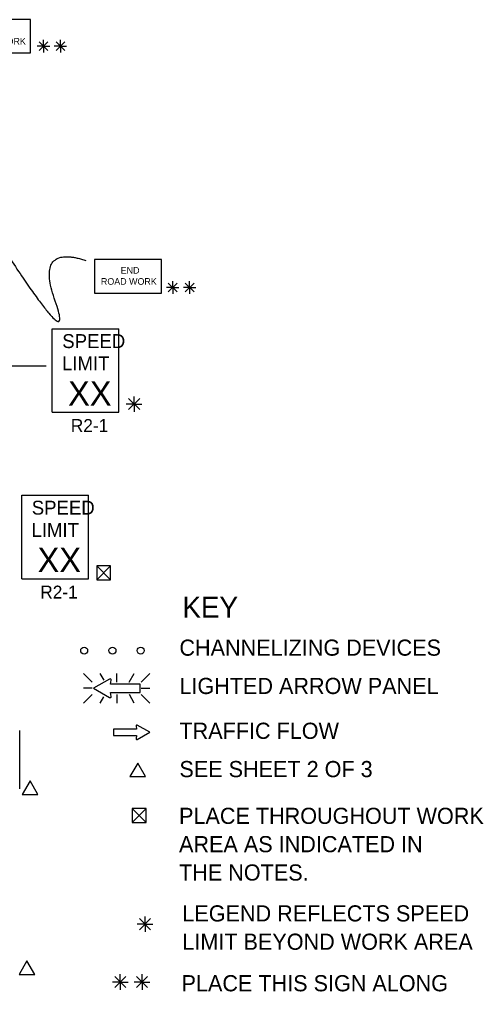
# Model space of a CAD drawing. Extents: x 16486 to 19505, y 5576 to 6998.
# Drawn here: x 17161 to 17428, y 6304 to 6864 of the extents above; entities that cross this region are included whole.
import ezdxf

# ---------------------------------------------------------------- set-up
doc = ezdxf.new("R2010")
doc.units = 0
for name, color, linetype in [('MT_SCRATCH_LEVEL_E', 7, 'Continuous'), ('TRAFFIC_SIGNS_PR', 7, 'Continuous'), ('TYPICAL_TEXT_DIMEN_EX', 7, 'Continuous'), ('TYPICAL_TEXT_DIMEN_PR', 7, 'Continuous')]:
    doc.layers.add(name, color=color, linetype=linetype)

msp = doc.modelspace()

# ---------------------------------------------------------------- linework, layer by layer
at = {"layer": 'MT_SCRATCH_LEVEL_E'}
for p, q in [((17235.64, 6453.62), (17228.4, 6457.73)), ((17228.03, 6455.48), (17214.78, 6455.48)), ((17214.78, 6455.48), (17214.78, 6451.73)), ((17227.72, 6457.25), (17228.03, 6455.48)), ((17228.4, 6449.48), (17235.64, 6453.62)), ((17214.78, 6451.73), (17228.03, 6451.73)), ((17228.03, 6451.73), (17227.72, 6449.95))]:
    msp.add_line(p, q, dxfattribs=at)
for centre, start, end in [((17228.18, 6457.33), 60.4248, 189.9638), ((17228.18, 6449.89), 170.0362, 299.7731)]:
    msp.add_arc(centre, 0.463, start, end, dxfattribs=at)
at = {"layer": 'TRAFFIC_SIGNS_PR'}
for p, q in [((17179.45, 6685.93), (17217.85, 6685.93)), ((17179.45, 6637.93), (17179.45, 6685.93)), ((17217.85, 6637.93), (17217.85, 6685.93)), ((17179.45, 6637.93), (17217.85, 6637.93)), ((17161.88, 6590.04), (17200.28, 6590.04)), ((17161.88, 6542.04), (17161.88, 6590.04)), ((17200.28, 6542.04), (17200.28, 6590.04)), ((17161.88, 6542.04), (17200.28, 6542.04)), ((17197.49, 6487.43), (17202.43, 6482.5)), ((17209.26, 6483.61), (17207.05, 6487.44)), ((17216.58, 6482.5), (17216.58, 6487.44)), ((17223.81, 6482.5), (17226.66, 6487.44)), ((17230.72, 6482.5), (17235.66, 6487.44)), ((17202.43, 6478.94), (17197.49, 6478.94)), ((17197.49, 6470.46), (17202.43, 6475.39)), ((17216.58, 6475.39), (17216.58, 6470.45)), ((17226.7, 6470.45), (17223.85, 6475.39)), ((17230.72, 6478.94), (17235.66, 6478.94)), ((17230.72, 6475.39), (17235.66, 6470.45)), ((17207, 6470.45), (17209.12, 6474.12)), ((17160.55, 6454.67), (17160.55, 6421.07))]:
    msp.add_line(p, q, dxfattribs=at)
for points in [[(17128.46, 6844.75), (17166.86, 6844.75), (17166.86, 6863.95), (17128.46, 6863.95)], [(17203.87, 6706.48), (17242.27, 6706.48), (17242.27, 6725.68), (17203.87, 6725.68)]]:
    msp.add_lwpolyline(points, close=True, dxfattribs=at)
for points in [[(17212.5, 6484.22), (17203.21, 6478.94), (17212.51, 6473.62)], [(17213.38, 6474.25), (17212.98, 6476.52), (17229.99, 6476.52), (17229.99, 6481.32), (17212.98, 6481.32), (17213.38, 6483.6)]]:
    msp.add_lwpolyline(points, dxfattribs=at)
for centre in [(17197.83, 6500.63), (17214.13, 6500.63), (17230.43, 6500.63)]:
    msp.add_circle(centre, 2, dxfattribs=at)
for centre, radius, start, end in [((17212.79, 6483.7), 0.598, 350.7308, 118.8916), ((17212.79, 6474.15), 0.597, 241.4833, 9.9593)]:
    msp.add_arc(centre, radius, start, end, dxfattribs=at)
at = {"layer": 'TYPICAL_TEXT_DIMEN_PR'}
for p, q in [((17171.86, 6851.12), (17176.96, 6846.02)), ((17176.96, 6851.12), (17171.86, 6846.02)), ((17174.41, 6848.57), (17174.41, 6852.14)), ((17181.61, 6851.12), (17186.71, 6846.02)), ((17186.71, 6851.12), (17181.61, 6846.02)), ((17184.16, 6848.57), (17184.16, 6852.14)), ((17174.41, 6848.57), (17170.79, 6848.57)), ((17174.41, 6848.57), (17176.96, 6848.57)), ((17174.41, 6848.57), (17177.99, 6848.57)), ((17174.41, 6848.57), (17174.41, 6844.97)), ((17184.16, 6848.57), (17180.53, 6848.57)), ((17184.16, 6848.57), (17186.71, 6848.57)), ((17184.16, 6848.57), (17187.74, 6848.57)), ((17184.16, 6848.57), (17184.16, 6844.97)), ((17248.82, 6709.68), (17245.19, 6709.68)), ((17246.27, 6712.23), (17251.37, 6707.13)), ((17251.37, 6712.23), (17246.27, 6707.13)), ((17248.82, 6709.68), (17248.82, 6713.25)), ((17248.82, 6709.68), (17251.37, 6709.68)), ((17248.82, 6709.68), (17252.4, 6709.68)), ((17248.82, 6709.68), (17248.82, 6706.08)), ((17258.57, 6709.68), (17254.94, 6709.68)), ((17261.12, 6712.23), (17256.01, 6707.13)), ((17256.02, 6712.23), (17261.12, 6707.13)), ((17258.57, 6709.68), (17258.57, 6713.25)), ((17258.57, 6709.68), (17261.12, 6709.68)), ((17258.57, 6709.68), (17262.15, 6709.68)), ((17258.57, 6709.68), (17258.57, 6706.08)), ((17142.7, 6664.64), (17175.9, 6664.64)), ((17142.7, 6664.64), (17175.9, 6664.64)), ((17142.7, 6664.64), (17175.9, 6664.64)), ((17226.64, 6642.55), (17222.11, 6642.55)), ((17223.45, 6645.73), (17229.83, 6639.36)), ((17229.83, 6645.73), (17223.45, 6639.36)), ((17226.64, 6642.55), (17226.64, 6647)), ((17226.64, 6642.55), (17229.83, 6642.55)), ((17226.64, 6642.55), (17231.12, 6642.55)), ((17226.64, 6642.55), (17226.64, 6638.05)), ((17205.07, 6549.36), (17213.07, 6541.36)), ((17205.07, 6541.36), (17213.07, 6549.36)), ((17225.49, 6409.76), (17233.49, 6401.76)), ((17225.49, 6401.76), (17233.49, 6409.76)), ((17229.73, 6346.37), (17236.1, 6340)), ((17236.1, 6346.37), (17229.73, 6340)), ((17232.92, 6343.19), (17232.92, 6347.64)), ((17232.92, 6343.19), (17228.38, 6343.19)), ((17232.92, 6343.19), (17236.1, 6343.19)), ((17232.92, 6343.19), (17237.39, 6343.19)), ((17232.92, 6343.19), (17232.92, 6338.69)), ((17215.44, 6313.03), (17221.81, 6306.66)), ((17221.81, 6313.03), (17215.44, 6306.66)), ((17218.63, 6309.85), (17218.63, 6314.3)), ((17234.37, 6313.03), (17227.99, 6306.66)), ((17228, 6313.03), (17234.37, 6306.66)), ((17231.18, 6309.85), (17231.18, 6314.3)), ((17218.63, 6309.85), (17214.1, 6309.85)), ((17218.63, 6309.85), (17221.81, 6309.85)), ((17218.63, 6309.85), (17223.1, 6309.85)), ((17218.63, 6309.85), (17218.63, 6305.35)), ((17231.18, 6309.85), (17226.65, 6309.85)), ((17231.18, 6309.85), (17234.37, 6309.85)), ((17231.18, 6309.85), (17235.66, 6309.85)), ((17231.18, 6309.85), (17231.18, 6305.35))]:
    msp.add_line(p, q, dxfattribs=at)
for points in [[(17205.07, 6549.36), (17205.07, 6541.36), (17213.07, 6541.36), (17213.07, 6549.36)], [(17228.71, 6435.91), (17224.18, 6428.08), (17233.23, 6428.08)], [(17166.67, 6425.66), (17162.15, 6417.82), (17171.2, 6417.82)], [(17225.49, 6409.76), (17225.49, 6401.76), (17233.49, 6401.76), (17233.49, 6409.76)], [(17164.86, 6322.07), (17160.34, 6314.24), (17169.39, 6314.24)]]:
    msp.add_lwpolyline(points, close=True, dxfattribs=at)
msp.add_open_spline([(17154.48, 6727.28), (17192.72, 6669.11), (17169.5, 6734.81), (17198.86, 6725.23)], degree=2, dxfattribs=at)

# ---------------------------------------------------------------- texts
at = {"layer": 'TRAFFIC_SIGNS_PR'}
for s, height, p in [('ROAD WORK', 3.831, (17132.07, 6849.49)), ('END', 3.831, (17218.87, 6717.6)), ('ROAD WORK', 3.831, (17207.48, 6711.22)), ('SPEED', 8, (17185.22, 6674.79)), ('LIMIT', 8, (17185.06, 6661.99)), ('XX', 14.031, (17188.56, 6641.69)), ('R2-1', 7.44, (17190.13, 6626.49)), ('SPEED', 8, (17167.64, 6578.9)), ('LIMIT', 8, (17167.48, 6566.1)), ('XX', 14.031, (17170.99, 6545.8)), ('R2-1', 7.44, (17172.55, 6530.6))]:
    msp.add_text(s, height=height, dxfattribs=at).set_placement(p)
at = {"layer": 'TYPICAL_TEXT_DIMEN_EX'}
for s, height, p in [('KEY', 12, (17254.34, 6519.6)), ('CHANNELIZING DEVICES', 9.3, (17252.68, 6497.69)), ('LIGHTED ARROW PANEL', 9.3, (17252.68, 6475.64)), ('TRAFFIC FLOW', 9.3, (17252.68, 6449.84)), ('SEE SHEET 2 OF 3', 9.3, (17252.68, 6427.79)), ('PLACE THROUGHOUT WORK', 9.3, (17252.47, 6400.87)), ('AREA AS INDICATED IN', 9.3, (17252.47, 6384.57)), ('THE NOTES.', 9.3, (17252.47, 6368.27)), ('LEGEND REFLECTS SPEED', 9.3, (17254.37, 6344.72)), ('LIMIT BEYOND WORK AREA', 9.3, (17254.37, 6328.42)), ('PLACE THIS SIGN ALONG', 9.3, (17253.92, 6304.51))]:
    msp.add_text(s, height=height, dxfattribs=at).set_placement(p)

doc.saveas('drawing.dxf')
